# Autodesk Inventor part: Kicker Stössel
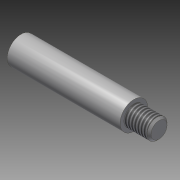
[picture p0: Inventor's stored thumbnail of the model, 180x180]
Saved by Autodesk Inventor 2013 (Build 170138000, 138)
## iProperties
Created: 2012-07
Part Number: Kicker Stössel
Material: Stahl
Document SubType Name: Modeling
Designer: rYan
Mass: 34.4266 g
Surface Area: 19.8211 cm^2
Volume: 4.38555 cm^3
Density: 7.85 g/cm^3
Author: rYan
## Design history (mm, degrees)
sketch "Skizze1"
  geometry: L1 (-27.5, 0)-(-27.5, 5.5); L2 (-27.5, 5.5)-(17.5, 5.5); L3 (17.5, 5.5)-(17.5, 4); L4 (17.5, 4)-(27.5, 4); L5 (27.5, 4)-(27.5, 0); L6 (27.5, 0)-(-27.5, 0); L7 (-38.5, 0)-(38.5, 0) reference; L8 (0, 6.6)-(0, -1.1) reference; 1 further point
  constraints: 12 end point, 4 parallel, 1 collinear, 1 perpendicular, 1 vertical, 1 other
  dimensions: "d0" = 55 distance of L5.end L1.start; "d2" = 10 distance of L3.end L4.end; "d3" = 11 diameter of L2 L6; "d4" = 8 diameter of L4 L6
revolve "Umdrehung1" sketch "Skizze1" stored, may be unused: angle "d5" = 90 deg
feature "Gewinde1" dims "d6" = 10, "d7" = 0
sketch "Skizze2"
  geometry: C1 r 5.5 at (0, 0) reference; 2 further points
  constraints: 1 coincident
hole "Bohrung1" sketch "Skizze2" at (0, 0) diameter "d8" = 4.917; stored, may be unused: countersink angle "d12" = 90 deg, drill point angle "d14" = 118 deg; dims "d9" = 8, "d10" = 4, "d11" = 2, "d13" = 12
chamfer "Fase1" distance "d15" = 0.8; stored, may be unused: second distance "d16" = 2, angle "d17" = 45 deg
chamfer "Fase2" distance "d18" = 0.8; stored, may be unused: second distance "d19" = 2, angle "d20" = 45 deg
node "Volumenkörper1"
